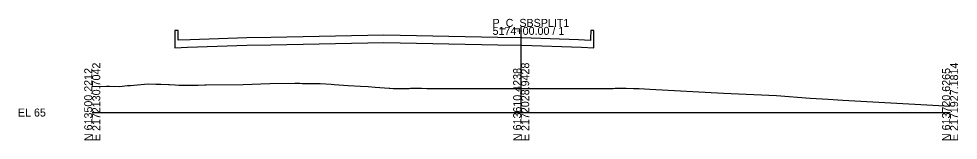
# Model space of a CAD drawing. Extents: x -26 to 1303, y -3010 to 12023.
# Drawn here: x -25.7 to 302.8, y 1490.3 to 1532.8 of the extents above; entities that cross this region are included whole.
import ezdxf

# ---------------------------------------------------------------- set-up
doc = ezdxf.new("R2010")
doc.units = 0
for name, color, linetype in [('RD_GPK_XS_Cell', 7, 'Continuous'), ('RD_PD_Final_TrvlWay', 7, 'Continuous'), ('RD_XS_ExGround', 7, 'Continuous')]:
    doc.layers.add(name, color=color, linetype=linetype)

msp = doc.modelspace()

# ---------------------------------------------------------------- linework, layer by layer
at = {"layer": 'RD_GPK_XS_Cell'}
for p, q in [((150, 1500), (150, 1530)), ((0, 1500), (150, 1500)), ((150, 1500), (300, 1500))]:
    msp.add_line(p, q, dxfattribs=at)
at = {"layer": 'RD_PD_Final_TrvlWay'}
msp.add_lwpolyline([(33.29, 1522.85), (54.1, 1523.57), (62.46, 1523.74), (102, 1524.53), (141.82, 1523.73), (150.22, 1523.56), (171.04, 1522.84), (175.43, 1522.69), (175.43, 1523.75), (175.43, 1528.78), (175.24, 1528.78), (174.31, 1528.78), (174.24, 1525.89), (174.22, 1525.28), (170.04, 1525.43), (150.22, 1526.12), (141.82, 1526.29), (102, 1527.09), (62.46, 1526.3), (54.1, 1526.13), (34.29, 1525.44), (30.1, 1525.29), (30.09, 1525.9), (30.02, 1528.79), (29.83, 1528.79), (28.9, 1528.79), (28.9, 1523.76), (28.9, 1522.7), (33.29, 1522.85)], dxfattribs=at)
at = {"layer": 'RD_XS_ExGround'}
msp.add_lwpolyline([(0, 1509.09), (5.03, 1509.23), (6.02, 1509.24), (9.55, 1509.17), (12.36, 1509.42), (13.38, 1509.5), (14.49, 1509.61), (19.53, 1510.07), (22.25, 1509.99), (23.42, 1509.91), (24.04, 1509.89), (26.63, 1509.84), (27.02, 1509.88), (29.03, 1509.66), (30.26, 1509.6), (30.79, 1509.6), (33.46, 1509.63), (34.18, 1509.63), (36.4, 1509.62), (37.06, 1509.61), (39.34, 1509.68), (39.85, 1509.67), (52.82, 1509.88), (62.15, 1510.19), (70.79, 1510.29), (72.63, 1510.3), (73.54, 1510.23), (79.52, 1510.21), (79.69, 1510.21), (83.57, 1509.92), (84.56, 1509.84), (89.54, 1509.51), (93.81, 1509.25), (96.51, 1509.14), (98.94, 1508.94), (103.88, 1508.52), (104.05, 1508.51), (105.18, 1508.47), (110.78, 1508.47), (111.35, 1508.5), (111.49, 1508.5), (115.18, 1508.58), (116.98, 1508.47), (119.01, 1508.47), (119.17, 1508.47), (132.45, 1508.47), (132.46, 1508.47), (132.47, 1508.47), (132.49, 1508.47), (166.56, 1508.47), (180.86, 1508.47), (182.01, 1508.47), (182.14, 1508.47), (182.91, 1508.58), (186.59, 1508.58), (186.76, 1508.56), (189.23, 1508.47), (190.64, 1508.47), (190.64, 1508.47), (191.25, 1508.41), (195.04, 1508.24), (220.73, 1506.84), (239.34, 1505.93), (251.1, 1505.01), (257.33, 1504.64), (262.51, 1504.31), (296.09, 1502.49), (300, 1502.24)], dxfattribs=at)

# ---------------------------------------------------------------- texts
at = {"layer": 'RD_GPK_XS_Cell'}
for s, p in [('P_C_SBSPLIT1', (140, 1530)), ('5174+00.00 / 1', (140, 1527.2)), ('EL 65', (-26, 1498.6))]:
    msp.add_text(s, height=2.8, dxfattribs=at).set_placement(p)
for s, p in [('N 613500.2212', (0, 1490)), ('E 2172130.7042', (2.8, 1490)), ('N 613610.4238', (150, 1490)), ('E 2172028.9428', (152.8, 1490)), ('N 613720.6265', (300, 1490)), ('E 2171927.1814', (302.8, 1490))]:
    msp.add_text(s, height=2.8, rotation=90, dxfattribs=at).set_placement(p)

doc.saveas('drawing.dxf')
